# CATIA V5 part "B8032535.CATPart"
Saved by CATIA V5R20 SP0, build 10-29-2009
Part number: B8032535
Revision: 12
Definition: design
Nomenclature: B8032535
Source: made
Description: NOT SPECIFIED
Bounding box of the stored display mesh (mm): x -20 to 20, y -20 to 20, z 0 to 35
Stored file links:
  C:\Users\Utente\Desktop\3D files B803\B8032535.CATPart
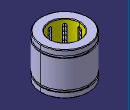
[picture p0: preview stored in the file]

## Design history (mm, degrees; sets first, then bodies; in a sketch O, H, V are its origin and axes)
Body1 "MANIFOLD_SOLID_BREP #38" (main body)
  Solid1: solid without history
Body2 "MANIFOLD_SOLID_BREP #76"
  Solid2: solid without history
Body3 "MANIFOLD_SOLID_BREP #114"
  Solid3: solid without history
Body4 "MANIFOLD_SOLID_BREP #152"
  Solid4: solid without history
Body5 "MANIFOLD_SOLID_BREP #190"
  Solid5: solid without history
Body6 "MANIFOLD_SOLID_BREP #228"
  Solid6: solid without history
Body7 "MANIFOLD_SOLID_BREP #266"
  Solid7: solid without history
Body8 "MANIFOLD_SOLID_BREP #304"
  Solid8: solid without history
Body9 "MANIFOLD_SOLID_BREP #2420"
  Solid9: solid without history
Body10 "MANIFOLD_SOLID_BREP #2458"
  Solid10: solid without history
Body11 "MANIFOLD_SOLID_BREP #2496"
  Solid11: solid without history
Body12 "MANIFOLD_SOLID_BREP #2534"
  Solid12: solid without history
Body13 "MANIFOLD_SOLID_BREP #2572"
  Solid13: solid without history
Body14 "MANIFOLD_SOLID_BREP #2610"
  Solid14: solid without history
Body15 "MANIFOLD_SOLID_BREP #2648"
  Solid15: solid without history
Body16 "MANIFOLD_SOLID_BREP #2686"
  Solid16: solid without history
Body17 "MANIFOLD_SOLID_BREP #2724"
  Solid17: solid without history
Body18 "MANIFOLD_SOLID_BREP #2762"
  Solid18: solid without history
Body19 "MANIFOLD_SOLID_BREP #2800"
  Solid19: solid without history
Body20 "MANIFOLD_SOLID_BREP #2838"
  Solid20: solid without history
Body21 "MANIFOLD_SOLID_BREP #2876"
  Solid21: solid without history
Body22 "MANIFOLD_SOLID_BREP #2914"
  Solid22: solid without history
Body23 "MANIFOLD_SOLID_BREP #2952"
  Solid23: solid without history
Body24 "MANIFOLD_SOLID_BREP #2990"
  Solid24: solid without history
Body25 "MANIFOLD_SOLID_BREP #3028"
  Solid25: solid without history
Body26 "MANIFOLD_SOLID_BREP #3066"
  Solid26: solid without history
Body27 "MANIFOLD_SOLID_BREP #3104"
  Solid27: solid without history
Body28 "MANIFOLD_SOLID_BREP #3142"
  Solid28: solid without history
Body29 "MANIFOLD_SOLID_BREP #3180"
  Solid29: solid without history
Body30 "MANIFOLD_SOLID_BREP #3218"
  Solid30: solid without history
Body31 "MANIFOLD_SOLID_BREP #3256"
  Solid31: solid without history
Body32 "MANIFOLD_SOLID_BREP #3294"
  Solid32: solid without history
Body33 "MANIFOLD_SOLID_BREP #3332"
  Solid33: solid without history
Body34 "MANIFOLD_SOLID_BREP #3370"
  Solid34: solid without history
Body35 "MANIFOLD_SOLID_BREP #3408"
  Solid35: solid without history
Body36 "MANIFOLD_SOLID_BREP #3446"
  Solid36: solid without history
Body37 "MANIFOLD_SOLID_BREP #3484"
  Solid37: solid without history
Body38 "MANIFOLD_SOLID_BREP #3522"
  Solid38: solid without history
Body39 "MANIFOLD_SOLID_BREP #3560"
  Solid39: solid without history
Body40 "MANIFOLD_SOLID_BREP #3598"
  Solid40: solid without history
Body41 "MANIFOLD_SOLID_BREP #3636"
  Solid41: solid without history
Body42 "MANIFOLD_SOLID_BREP #3674"
  Solid42: solid without history
Body43 "MANIFOLD_SOLID_BREP #3712"
  Solid43: solid without history
Body44 "MANIFOLD_SOLID_BREP #3750"
  Solid44: solid without history
Body45 "MANIFOLD_SOLID_BREP #3788"
  Solid45: solid without history
Body46 "MANIFOLD_SOLID_BREP #3826"
  Solid46: solid without history
Body47 "MANIFOLD_SOLID_BREP #3864"
  Solid47: solid without history
Body48 "MANIFOLD_SOLID_BREP #3902"
  Solid48: solid without history
Body49 "MANIFOLD_SOLID_BREP #3940"
  Solid49: solid without history
Body50 "MANIFOLD_SOLID_BREP #3978"
  Solid50: solid without history
Body51 "MANIFOLD_SOLID_BREP #4016"
  Solid51: solid without history
Body52 "MANIFOLD_SOLID_BREP #4054"
  Solid52: solid without history
Body53 "MANIFOLD_SOLID_BREP #4092"
  Solid53: solid without history
Body54 "MANIFOLD_SOLID_BREP #4130"
  Solid54: solid without history
Body55 "MANIFOLD_SOLID_BREP #4168"
  Solid55: solid without history
Body56 "MANIFOLD_SOLID_BREP #4206"
  Solid56: solid without history
Body57 "MANIFOLD_SOLID_BREP #4244"
  Solid57: solid without history
Body58 "MANIFOLD_SOLID_BREP #4282"
  Solid58: solid without history
Body59 "MANIFOLD_SOLID_BREP #4320"
  Solid59: solid without history
Body60 "MANIFOLD_SOLID_BREP #4358"
  Solid60: solid without history
Body61 "MANIFOLD_SOLID_BREP #4396"
  Solid61: solid without history
Body62 "MANIFOLD_SOLID_BREP #4434"
  Solid62: solid without history
Body63 "MANIFOLD_SOLID_BREP #4472"
  Solid63: solid without history
Body64 "MANIFOLD_SOLID_BREP #4510"
  Solid64: solid without history
Body65 "MANIFOLD_SOLID_BREP #4548"
  Solid65: solid without history
Body66 "MANIFOLD_SOLID_BREP #4586"
  Solid66: solid without history
Body67 "MANIFOLD_SOLID_BREP #4624"
  Solid67: solid without history
Body68 "MANIFOLD_SOLID_BREP #4662"
  Solid68: solid without history
Body69 "MANIFOLD_SOLID_BREP #4700"
  Solid69: solid without history
Body70 "MANIFOLD_SOLID_BREP #4738"
  Solid70: solid without history
Body71 "MANIFOLD_SOLID_BREP #4776"
  Solid71: solid without history
Body72 "MANIFOLD_SOLID_BREP #4814"
  Solid72: solid without history
Body73 "MANIFOLD_SOLID_BREP #4852"
  Solid73: solid without history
